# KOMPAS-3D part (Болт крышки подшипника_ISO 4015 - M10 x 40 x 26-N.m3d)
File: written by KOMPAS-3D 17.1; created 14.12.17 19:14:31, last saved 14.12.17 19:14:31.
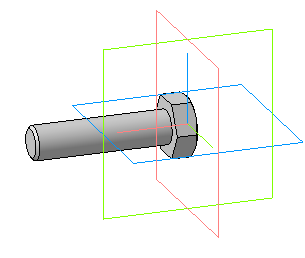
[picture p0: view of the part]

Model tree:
1. Операция без истории:1  (labels: Болт крышки подшипника_ISO 4015 - M10 x 40 x 26-N)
